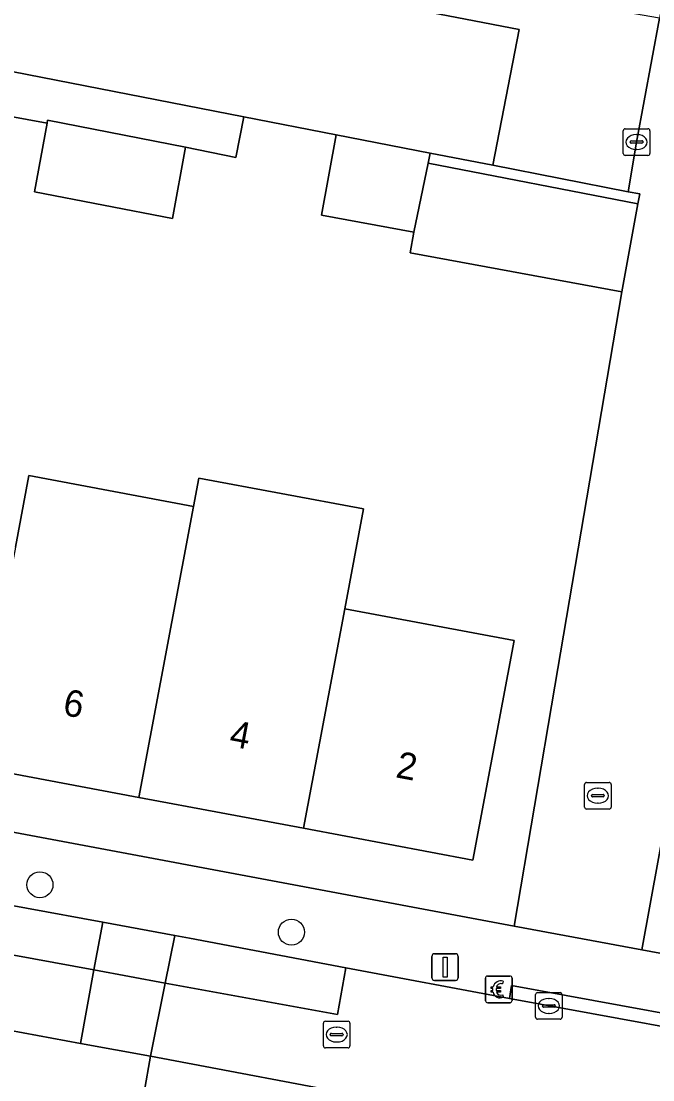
# Model space of a CAD drawing. Extents: x 161402 to 161933, y 381647 to 382315.
# Drawn here: x 161838.49 to 161862.24, y 381943.55 to 381983.35 of the extents above; entities that cross this region are included whole.
import ezdxf

# ---------------------------------------------------------------- set-up
doc = ezdxf.new("R2010")
doc.units = 0
for name, color, linetype in [('IMGEO_Betaalautomaat', 7, 'Continuous'), ('IMGEO_Boom', 7, 'Continuous'), ('IMGEO_Erf', 7, 'Continuous'), ('IMGEO_Kolk', 7, 'Continuous'), ('IMGEO_Lichtmast', 7, 'Continuous'), ('IMGEO_Muur', 7, 'Continuous'), ('IMGEO_Pand', 7, 'Continuous'), ('IMGEO_Pand_nummerreeks', 7, 'Continuous'), ('IMGEO_Parkeervlak_gesloten', 7, 'Continuous'), ('IMGEO_Parkeervlak_open', 7, 'Continuous'), ('IMGEO_Rijbaan_lokaal_gesloten', 7, 'Continuous'), ('IMGEO_Rijbaan_lokaal_open', 7, 'Continuous'), ('IMGEO_Rioolput', 7, 'Continuous'), ('IMGEO_Voetpad_open', 7, 'Continuous')]:
    doc.layers.add(name, color=color, linetype=linetype)

msp = doc.modelspace()

# ---------------------------------------------------------------- linework, layer by layer
at = {"layer": 'IMGEO_Betaalautomaat'}
for p, q in [((161855.951, 381946.525), (161855.951, 381947.366)), ((161855.951, 381947.366), (161855.951, 381946.525)), ((161856.026, 381947.449), (161856.867, 381947.449)), ((161856.867, 381947.449), (161856.026, 381947.449)), ((161856.613, 381947.254), (161856.596, 381947.154)), ((161856.95, 381947.375), (161856.95, 381946.534)), ((161856.95, 381946.534), (161856.95, 381947.375)), ((161856.234, 381946.913), (161856.234, 381946.981)), ((161856.355, 381946.981), (161856.355, 381946.913)), ((161856.876, 381946.45), (161856.035, 381946.45)), ((161856.035, 381946.45), (161856.876, 381946.45)), ((161856.6, 381946.748), (161856.622, 381946.661))]:
    msp.add_line(p, q, dxfattribs=at)
for points in [[(161856.234, 381946.981), (161856.165, 381946.981), (161856.165, 381947.05), (161856.244, 381947.05)], [(161856.239, 381946.844), (161856.165, 381946.844), (161856.165, 381946.913), (161856.234, 381946.913)], [(161856.366, 381947.05), (161856.513, 381947.05), (161856.513, 381946.981), (161856.355, 381946.981)], [(161856.355, 381946.913), (161856.513, 381946.913), (161856.513, 381946.844), (161856.369, 381946.844)]]:
    msp.add_lwpolyline(points, dxfattribs=at)
for centre, radius, start, end in [((161856.029, 381947.372), 0.0779, 92.4484, 184.2845), ((161856.029, 381947.372), 0.0779, 92.4484, 184.2845), ((161856.527, 381946.974), 0.293, 73.014, 165.0139), ((161856.533, 381946.987), 0.179, 69.3236, 159.5683), ((161856.873, 381947.372), 0.0779, 2.4484, 94.2845), ((161856.873, 381947.372), 0.0779, 2.4484, 94.2845), ((161856.5, 381946.899), 0.267, 191.8096, 297.0389), ((161856.533, 381946.914), 0.179, 202.7625, 291.8693), ((161856.029, 381946.528), 0.0779, 182.4484, 274.2845), ((161856.029, 381946.528), 0.0779, 182.4484, 274.2845), ((161856.873, 381946.528), 0.0779, 272.4484, 4.2845), ((161856.873, 381946.528), 0.0779, 272.4484, 4.2845)]:
    msp.add_arc(centre, radius, start, end, dxfattribs=at)
at = {"layer": 'IMGEO_Boom'}
for centre in [(161839.199, 381950.883), (161848.654, 381949.101)]:
    msp.add_circle(centre, 0.489, dxfattribs=at)
at = {"layer": 'IMGEO_Erf'}
for points in [[(161823.681, 381955.575), (161857.033, 381949.323), (161858.562, 381958.352), (161861.08, 381973.179), (161853.114, 381974.64), (161853.257, 381975.42), (161849.782, 381976.057), (161850.336, 381979.079), (161846.863, 381979.756), (161846.563, 381978.219), (161844.674, 381978.618), (161844.181, 381975.929), (161838.994, 381976.939), (161839.466, 381979.518), (161834.946, 381980.346)], [(161838.276, 381963.578), (161838.779, 381966.265), (161844.971, 381965.105), (161845.171, 381966.173), (161851.364, 381965.012), (161850.66, 381961.257), (161857.027, 381960.063), (161855.481, 381951.814), (161849.115, 381953.007), (161842.923, 381954.168), (161836.731, 381955.328)]]:
    msp.add_lwpolyline(points, dxfattribs=at)
msp.add_lwpolyline([(161856.229, 381977.931), (161853.869, 381978.391), (161853.792, 381978.018), (161861.686, 381976.481), (161861.755, 381976.855), (161861.321, 381976.94)], close=True, dxfattribs=at)
at = {"layer": 'IMGEO_Kolk'}
for p, q in [((161861.134, 381978.379), (161861.134, 381979.231)), ((161861.209, 381979.305), (161862.061, 381979.305)), ((161861.622, 381979.085), (161861.647, 381979.085)), ((161862.135, 381979.231), (161862.135, 381978.379)), ((161861.393, 381978.799), (161861.393, 381978.811)), ((161861.831, 381978.762), (161861.433, 381978.762)), ((161861.436, 381978.848), (161861.834, 381978.848)), ((161861.877, 381978.811), (161861.877, 381978.799)), ((161862.061, 381978.305), (161861.209, 381978.305)), ((161861.645, 381978.525), (161861.62, 381978.525)), ((161859.752, 381954.731), (161860.604, 381954.731)), ((161859.677, 381953.805), (161859.677, 381954.657)), ((161860.165, 381954.511), (161860.19, 381954.511)), ((161860.678, 381954.657), (161860.678, 381953.805)), ((161859.936, 381954.225), (161859.936, 381954.237)), ((161860.374, 381954.188), (161859.976, 381954.188)), ((161859.979, 381954.274), (161860.377, 381954.274)), ((161860.188, 381953.951), (161860.163, 381953.951)), ((161860.42, 381954.237), (161860.42, 381954.225)), ((161860.604, 381953.731), (161859.752, 381953.731)), ((161857.908, 381946.829), (161858.76, 381946.829)), ((161857.833, 381945.903), (161857.833, 381946.755)), ((161858.135, 381946.372), (161858.533, 381946.372)), ((161858.321, 381946.609), (161858.346, 381946.609)), ((161858.834, 381946.755), (161858.834, 381945.903)), ((161858.092, 381946.323), (161858.092, 381946.335)), ((161858.53, 381946.286), (161858.132, 381946.286)), ((161858.344, 381946.049), (161858.319, 381946.049)), ((161858.576, 381946.335), (161858.576, 381946.323)), ((161858.76, 381945.829), (161857.908, 381945.829))]:
    msp.add_line(p, q, dxfattribs=at)
for points in [[(161861.134, 381978.379), (161861.134, 381979.231)], [(161861.209, 381979.305), (161862.061, 381979.305)], [(161862.135, 381979.231), (161862.135, 381978.379)], [(161862.061, 381978.305), (161861.209, 381978.305)], [(161859.752, 381954.731), (161860.604, 381954.731)], [(161859.677, 381953.805), (161859.677, 381954.657)], [(161860.678, 381954.657), (161860.678, 381953.805)], [(161860.604, 381953.731), (161859.752, 381953.731)], [(161857.908, 381946.829), (161858.76, 381946.829)], [(161857.833, 381945.903), (161857.833, 381946.755)], [(161858.834, 381946.755), (161858.834, 381945.903)], [(161858.76, 381945.829), (161857.908, 381945.829)]]:
    msp.add_lwpolyline(points, dxfattribs=at)
for centre, radius, start, end in [((161861.211, 381979.229), 0.0765, 91.552, 178.448), ((161861.211, 381979.229), 0.0765, 91.552, 178.448), ((161862.059, 381979.229), 0.0765, 1.552, 88.448), ((161862.059, 381979.229), 0.0765, 1.552, 88.448), ((161861.433, 381978.808), 0.0403, 85.8775, 175.7526), ((161861.43, 381978.798), 0.0366, 178.938, 274.7102), ((161861.834, 381978.805), 0.043, 264.8664, 352.4533), ((161861.838, 381978.81), 0.0386, 1.7309, 96.639), ((161861.211, 381978.381), 0.0765, 181.552, 268.448), ((161861.211, 381978.381), 0.0765, 181.552, 268.448), ((161862.059, 381978.381), 0.0765, 271.552, 358.448), ((161862.059, 381978.381), 0.0765, 271.552, 358.448), ((161859.754, 381954.655), 0.0765, 91.552, 178.448), ((161859.754, 381954.655), 0.0765, 91.552, 178.448), ((161860.602, 381954.655), 0.0765, 1.552, 88.448), ((161860.602, 381954.655), 0.0765, 1.552, 88.448), ((161859.976, 381954.234), 0.0403, 85.8775, 175.7526), ((161859.973, 381954.224), 0.0366, 178.938, 274.7102), ((161860.377, 381954.231), 0.043, 264.8664, 352.4533), ((161860.381, 381954.236), 0.0386, 1.7309, 96.639), ((161859.754, 381953.807), 0.0765, 181.552, 268.448), ((161859.754, 381953.807), 0.0765, 181.552, 268.448), ((161860.602, 381953.807), 0.0765, 271.552, 358.448), ((161860.602, 381953.807), 0.0765, 271.552, 358.448), ((161857.91, 381946.753), 0.0765, 91.552, 178.448), ((161857.91, 381946.753), 0.0765, 91.552, 178.448), ((161858.758, 381946.753), 0.0765, 1.552, 88.448), ((161858.758, 381946.753), 0.0765, 1.552, 88.448), ((161858.132, 381946.332), 0.0403, 85.8775, 175.7526), ((161858.537, 381946.334), 0.0386, 1.7309, 96.639), ((161858.129, 381946.322), 0.0366, 178.938, 274.7102), ((161858.533, 381946.329), 0.043, 264.8664, 352.4533), ((161857.91, 381945.905), 0.0765, 181.552, 268.448), ((161857.91, 381945.905), 0.0765, 181.552, 268.448), ((161858.758, 381945.905), 0.0765, 271.552, 358.448), ((161858.758, 381945.905), 0.0765, 271.552, 358.448)]:
    msp.add_arc(centre, radius, start, end, dxfattribs=at)
for centre, major_axis, ratio, start_param, end_param in [((161861.621, 381978.805), (-0.387, 0.002), 0.722429, 4.712389, 7.853982), ((161861.646, 381978.805), (-0.39, 0.002), 0.717154, 1.570796, 4.712389), ((161860.164, 381954.231), (-0.387, 0.002), 0.722429, 4.712389, 7.853982), ((161860.189, 381954.231), (-0.39, 0.002), 0.717154, 1.570796, 4.712389), ((161858.32, 381946.329), (-0.387, 0.002), 0.722429, 4.712389, 7.853982), ((161858.345, 381946.329), (-0.39, 0.002), 0.717154, 1.570796, 4.712389)]:
    msp.add_ellipse(centre, major_axis=major_axis, ratio=ratio, start_param=start_param, end_param=end_param, dxfattribs=at)
at = {"layer": 'IMGEO_Lichtmast'}
for p, q in [((161853.935, 381947.39), (161853.935, 381948.19)), ((161853.935, 381948.19), (161853.935, 381947.39)), ((161854.035, 381948.29), (161854.825, 381948.29)), ((161854.825, 381948.29), (161854.035, 381948.29)), ((161854.925, 381948.19), (161854.925, 381947.39)), ((161854.925, 381947.39), (161854.925, 381948.19)), ((161854.825, 381947.29), (161854.035, 381947.29)), ((161854.035, 381947.29), (161854.825, 381947.29))]:
    msp.add_line(p, q, dxfattribs=at)
msp.add_lwpolyline([(161854.355, 381948.165), (161854.505, 381948.165), (161854.505, 381947.415), (161854.355, 381947.415), (161854.355, 381948.165)], dxfattribs=at)
for centre, start, end in [((161854.035, 381948.19), 90, 180), ((161854.035, 381948.19), 90, 180), ((161854.825, 381948.19), 0, 90), ((161854.825, 381948.19), 360, 90), ((161854.035, 381947.39), 180, 270), ((161854.035, 381947.39), 180, 270), ((161854.825, 381947.39), 270, 0), ((161854.825, 381947.39), 270, 0)]:
    msp.add_arc(centre, 0.1, start, end, dxfattribs=at)
at = {"layer": 'IMGEO_Muur'}
msp.add_lwpolyline([(161860.954, 381972.49), (161858.562, 381958.352)], dxfattribs=at)
at = {"layer": 'IMGEO_Pand'}
for points in [[(161844.674, 381978.618), (161839.486, 381979.628), (161839.466, 381979.518), (161838.994, 381976.939), (161844.181, 381975.929)], [(161853.792, 381978.018), (161853.869, 381978.391), (161850.336, 381979.079), (161849.782, 381976.057), (161853.257, 381975.42)], [(161861.686, 381976.481), (161853.792, 381978.018), (161853.257, 381975.42), (161853.114, 381974.64), (161861.08, 381973.179)], [(161836.731, 381955.328), (161842.923, 381954.168), (161844.971, 381965.105), (161838.779, 381966.265), (161838.276, 381963.578)], [(161844.971, 381965.105), (161842.923, 381954.168), (161849.115, 381953.007), (161850.66, 381961.257), (161851.364, 381965.012), (161845.171, 381966.173)], [(161850.66, 381961.257), (161849.115, 381953.007), (161855.481, 381951.814), (161857.027, 381960.063)]]:
    msp.add_lwpolyline(points, close=True, dxfattribs=at)
msp.add_lwpolyline([(161874.288, 381954.778), (161866.008, 381959.287), (161864.117, 381960.973), (161864.023, 381960.454), (161861.825, 381948.441), (161882.328, 381944.651), (161882.378, 381944.986)], dxfattribs=at)
at = {"layer": 'IMGEO_Parkeervlak_gesloten'}
msp.add_lwpolyline([(161834.75, 381987.369), (161832.631, 381987.778), (161831.646, 381982.721), (161846.863, 381979.756), (161850.336, 381979.079), (161853.869, 381978.391), (161856.229, 381977.931), (161857.213, 381983.04)], close=True, dxfattribs=at)
at = {"layer": 'IMGEO_Parkeervlak_open'}
for points in [[(161835.816, 381950.524), (161826.853, 381952.245), (161826.511, 381950.381), (161841.229, 381947.681), (161841.561, 381949.474)], [(161844.266, 381948.98), (161841.561, 381949.474), (161841.229, 381947.681), (161843.908, 381947.189)], [(161850.705, 381947.765), (161844.817, 381948.879), (161844.266, 381948.98), (161843.908, 381947.189), (161850.381, 381946.002)]]:
    msp.add_lwpolyline(points, close=True, dxfattribs=at)
at = {"layer": 'IMGEO_Rijbaan_lokaal_gesloten'}
msp.add_lwpolyline([(161834.474, 381994.007), (161830.987, 381994.574), (161828.968, 381983.243), (161831.646, 381982.721), (161832.631, 381987.778), (161834.75, 381987.369), (161857.213, 381983.04), (161856.229, 381977.931), (161861.321, 381976.94), (161861.636, 381978.805), (161862.491, 381983.458), (161857.448, 381984.357), (161864.341, 382023.003)], dxfattribs=at)
at = {"layer": 'IMGEO_Rijbaan_lokaal_open'}
for points in [[(161866.912, 381976.352), (161869.626, 381991.167), (161871.026, 381998.811), (161866.018, 381999.693), (161865.428, 381999.797), (161863.999, 381991.661), (161862.491, 381983.458), (161861.636, 381978.805), (161861.321, 381976.94), (161861.755, 381976.855), (161861.686, 381976.481), (161861.08, 381973.179), (161858.562, 381958.352), (161857.033, 381949.323), (161861.825, 381948.441), (161864.023, 381960.454), (161864.117, 381960.973), (161864.865, 381965.088), (161865.345, 381967.728)], [(161843.908, 381947.189), (161841.229, 381947.681), (161840.719, 381944.921), (161843.358, 381944.434)], [(161870.982, 381944.038), (161868.335, 381944.505), (161867.265, 381944.7), (161856.849, 381946.602), (161850.705, 381947.765), (161850.381, 381946.002), (161843.908, 381947.189), (161843.358, 381944.434), (161851.839, 381942.835), (161855.435, 381942.157), (161856.984, 381941.865), (161861.026, 381941.093), (161870.929, 381939.2), (161877.762, 381937.889), (161882.94, 381936.934), (161883.165, 381936.881), (161884.023, 381941.644), (161882.997, 381941.882), (161882.653, 381940.012), (161870.647, 381942.219)]]:
    msp.add_lwpolyline(points, close=True, dxfattribs=at)
msp.add_lwpolyline([(161821.896, 381948.301), (161832.624, 381946.415), (161840.719, 381944.921), (161841.229, 381947.681), (161826.511, 381950.381), (161826.853, 381952.245)], dxfattribs=at)
at = {"layer": 'IMGEO_Rioolput'}
for p, q in [((161849.855, 381944.826), (161849.855, 381945.678)), ((161849.93, 381945.752), (161850.782, 381945.752)), ((161850.856, 381945.678), (161850.856, 381944.826)), ((161850.114, 381945.246), (161850.114, 381945.258)), ((161850.552, 381945.209), (161850.154, 381945.209)), ((161850.157, 381945.295), (161850.555, 381945.295)), ((161850.343, 381945.532), (161850.368, 381945.532)), ((161850.598, 381945.258), (161850.598, 381945.246)), ((161850.366, 381944.972), (161850.341, 381944.972)), ((161850.782, 381944.752), (161849.93, 381944.752))]:
    msp.add_line(p, q, dxfattribs=at)
for points in [[(161849.855, 381944.826), (161849.855, 381945.678)], [(161849.93, 381945.752), (161850.782, 381945.752)], [(161850.856, 381945.678), (161850.856, 381944.826)], [(161850.782, 381944.752), (161849.93, 381944.752)]]:
    msp.add_lwpolyline(points, dxfattribs=at)
for centre, radius, start, end in [((161849.932, 381945.676), 0.0765, 91.552, 178.448), ((161849.932, 381945.676), 0.0765, 91.552, 178.448), ((161850.78, 381945.676), 0.0765, 1.552, 88.448), ((161850.78, 381945.676), 0.0765, 1.552, 88.448), ((161850.154, 381945.255), 0.0403, 85.8775, 175.7526), ((161850.151, 381945.245), 0.0366, 178.938, 274.7102), ((161850.555, 381945.252), 0.043, 264.8664, 352.4533), ((161850.559, 381945.257), 0.0386, 1.7309, 96.639), ((161849.932, 381944.828), 0.0765, 181.552, 268.448), ((161849.932, 381944.828), 0.0765, 181.552, 268.448), ((161850.78, 381944.828), 0.0765, 271.552, 358.448), ((161850.78, 381944.828), 0.0765, 271.552, 358.448)]:
    msp.add_arc(centre, radius, start, end, dxfattribs=at)
for centre, major_axis, ratio, start_param, end_param in [((161850.342, 381945.252), (-0.387, 0.002), 0.722429, 4.712389, 7.853982), ((161850.367, 381945.252), (-0.39, 0.002), 0.717154, 1.570796, 4.712389)]:
    msp.add_ellipse(centre, major_axis=major_axis, ratio=ratio, start_param=start_param, end_param=end_param, dxfattribs=at)
at = {"layer": 'IMGEO_Voetpad_open'}
for points in [[(161831.646, 381982.721), (161828.968, 381983.243), (161828.609, 381981.506), (161834.946, 381980.346), (161839.466, 381979.518), (161839.486, 381979.628), (161844.674, 381978.618), (161846.563, 381978.219), (161846.863, 381979.756)], [(161856.934, 381947.094), (161856.849, 381946.602), (161867.265, 381944.7), (161867.35, 381945.192)], [(161840.719, 381944.921), (161832.624, 381946.415), (161832.192, 381943.9), (161832.159, 381943.741), (161842.874, 381941.733), (161843.358, 381944.434)]]:
    msp.add_lwpolyline(points, close=True, dxfattribs=at)
for points in [[(161861.825, 381948.441), (161857.033, 381949.323), (161823.681, 381955.575), (161822.45, 381956.505)], [(161825.144, 381952.573), (161826.853, 381952.245), (161835.816, 381950.524), (161841.561, 381949.474), (161844.266, 381948.98), (161844.817, 381948.879), (161850.705, 381947.765), (161856.849, 381946.602), (161856.934, 381947.094), (161867.35, 381945.192), (161867.265, 381944.7), (161868.335, 381944.505), (161870.982, 381944.038), (161878.707, 381942.675), (161882.65, 381941.962), (161882.997, 381941.882), (161884.023, 381941.644), (161884.434, 381944.363)], [(161882.378, 381944.986), (161882.328, 381944.651), (161861.825, 381948.441)], [(161884.172, 381936.679), (161883.165, 381936.881), (161882.94, 381936.934), (161877.762, 381937.889), (161870.929, 381939.2), (161861.026, 381941.093), (161860.933, 381940.603), (161855.342, 381941.66), (161851.746, 381942.34), (161851.839, 381942.835), (161843.358, 381944.434), (161842.874, 381941.733), (161842.921, 381941.724), (161844.317, 381941.463), (161854.463, 381939.508), (161854.619, 381939.456), (161855.327, 381939.321), (161860.503, 381938.326), (161878.948, 381934.818), (161878.246, 381931.217), (161883.878, 381930.136), (161884.914, 381936.489)]]:
    msp.add_lwpolyline(points, dxfattribs=at)

# ---------------------------------------------------------------- texts
at = {"layer": 'IMGEO_Pand_nummerreeks'}
for s, p in [('6', (161840.021, 381957.275)), ('4', (161846.283, 381956.102)), ('2', (161852.542, 381954.928))]:
    msp.add_text(s, height=1, rotation=349.3843, dxfattribs=at).set_placement(p)

doc.saveas('drawing.dxf')
